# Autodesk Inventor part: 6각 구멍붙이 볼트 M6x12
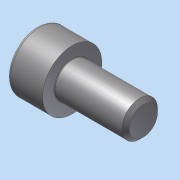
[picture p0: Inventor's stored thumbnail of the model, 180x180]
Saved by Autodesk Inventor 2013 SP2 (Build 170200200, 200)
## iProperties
Created: 2026-01
Part Number: 6각 구멍붙이 볼트 M6x12
Material: Generic
Document SubType Name: Modeling
Designer: a
Density: 1 g/cm^3
Author: a
변환 표준: STEP AP214IS
전처리기: Build: 200, Release: 2013 SP2 Update 6 - Date: Thu 07/17/2014
전송 단위: 밀리미터
불확실성: 0.01
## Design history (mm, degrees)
node "6각 구멍붙이 볼트 M6x121"
body "Solid1"
node "기준1"
